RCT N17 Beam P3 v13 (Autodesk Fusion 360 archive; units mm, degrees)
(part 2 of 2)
sketch "Sketch1" plane through (0, 0, 0) normal (0, 0, 1) x axis (1, 0, 0)
  line L1 (-16, -1.6) -> (-12, -1.6)
  line L2 (-16, 1.6) -> (-16, -1.6)
  line L3 (-12, 1.6) -> (-16, 1.6)
  line L4 (-12, -1.6) -> (-12, 1.6)
  line L5 (0, 1.73) -> (0, 2.6)
  line L6 (0, -1.73) -> (0, -2.6)
  line L7 (0, 4.3) -> (0, 2.6)
  line L8 (0, -4.3) -> (0, -2.6)
  line L9 (-7, 1.6) -> (-12, 1.6)
  line L10 (-7, -1.6) -> (-12, -1.6)
  line L11 (-7, -1.6) -> (-7, 1.6)
  line L12 (-4, 1.6) -> (-7, 1.6)
  line L13 (-4, -1.6) -> (-4, 1.6)
  line L14 (-7, -1.6) -> (-4, -1.6)
  line L15 (-4, 3.3) -> (-4, 1.6)
  line L16 (-16, 3.3) -> (-4, 3.3)
  line L17 (-16, 1.6) -> (-16, 3.3)
  line L18 (-16, 0) -> (0, 0)
  line L19 (-12, 3.3) -> (-12, 1.6)
  line L20 (-7, 3.3) -> (-7, 1.6)
  line L21 (-2.7568, 3.3) -> (-4, 3.3)
  line L22 (3.43, -3.43) -> (-3.43, -3.43)
  line L23 (3.43, 3.43) -> (3.43, -3.43)
  line L24 (-3.43, 3.43) -> (3.43, 3.43)
  line L25 (-3.43, -3.43) -> (-3.43, 3.43)
  line L26 (3.43, 3.43) -> (-3.43, -3.43)
  line L27 (-3.43, 3.43) -> (3.43, -3.43)
  circle C1 centre (0, 0) radius 1.625
  circle C2 centre (0, 0) radius 3
  circle C3 centre (0, 0) radius 2.6
  circle C4 centre (0, 0) radius 1.73
  circle C5 centre (0, 0) radius 4.3
  point P1 (0, 0)
  point P2 (0, 0)
  point P5 (0, 0)
  point P10 (0, 2.6)
  point P11 (0, -2.6)
  point P12 (0, 1.73)
  point P13 (0, -1.73)
  point P14 (-12, 0)
  point P3 (0, 0)
  point P4 (0, 0)
  point P15 (0, 0)
  point P16 (0, 4.3)
  point P17 (0, -4.3)
  point P18 (-7, -1.6)
  point P21 (-7, -1.6)
  point P8 (-16, 1.6)
  point P24 (-16, 1.6)
  point P25 (0, 0)
  point P26 (-16, 0)
  point P27 (-12, 3.3)
  point P28 (-7, 3.3)
  point P30 (-2.7568, 3.3)
  point P35 (0, 0)
  point P36 (0, -3.43)
  point P37 (0, -1.73)
  point P7 (-16, -1.6)
  point P9 (-12, 1.6)
  point P20 (-4, -1.6)
  point P23 (-16, 3.3)
  coincident P1 P2
  concentric C1 C2
  concentric C2 C3
  coincident P1 P5
  horizontal L1
  vertical L2
  horizontal L3
  coincident C3 P10
  coincident C3 P11
  coincident C4 P12
  coincident C4 P13
  vertical L4
  midpoint L4 P14
  coincident P3 L5
  coincident P4 L6
  vertical L5
  vertical L6
  horizontal P1 P14
  coincident P1 P15
  coincident C5 P16
  vertical L7
  coincident C5 P17
  parallel L7 L8
  perpendicular L4 L9
  perpendicular L4 L10
  perpendicular L11 L12
  perpendicular L12 L13
  perpendicular L13 L14
  coincident P18 P21
  perpendicular L12 L15
  perpendicular L15 L16
  perpendicular L16 L17
  coincident P8 P24
  coincident P2 P25
  midpoint L2 P26
  coincident L16 P27
  perpendicular L16 L19
  coincident L16 P28
  perpendicular L16 L20
  vertical L20
  coincident C5 P30
  perpendicular L15 L21
  perpendicular L22 L23
  parallel L22 L24
  parallel L23 L25
  horizontal L22
  coincident L26 P35
  coincident L27 P35
  coincident P5 P35
  midpoint L22 P36
  coincident P13 P37
  equal L22 L25
  dimension "d1" diameter C1 = 3.25
  dimension "d2" diameter C2 = 6
  dimension "d3" diameter C3 = 5.2 (= "heatset_entry")
  dimension "d4" distance C3 C4 = 0.87 (= "print_wall * 2")
  dimension "d11" distance P7 P8 = 3.2 (= "recip_thickness")
  dimension "d29" distance P8 P9 = 4
  dimension "d69" distance P11 P17 = 1.7
  dimension "d70" distance L4 P18 = 5
  dimension "d71" distance P20 P21 = 3
  dimension "d72" distance P23 P24 = 1.7
  dimension "d95" distance P15 L13 = 4
  dimension "d99" distance P36 P37 = 1.7
  dimension "d104" distance P15 L22 = 3.43
extrude "Extrude7" new body sketch "Sketch1" profile of C3 C4 L2 L3 L4 L5 L6 C5 L7 L8 L9 L11 L12 L13 L14 L15 L16 L17 L18 L19 L20 L21 along normal blind 8 (= "heatset_depth + 4 mm")
extrude "Extrude9" cut sketch "Sketch1" profile of C3 C4 L5 L6 L18 along normal blind 4 (= "heatset_depth")
chamfer "Chamfer8" distance 0.2 (= "heatset_taperby") distance 4 (= "heatset_depth")
chamfer "Chamfer9" distance 0.4
extrude "Extrude8" sketch "Sketch1" profile of L4 C5 L9 L11 L16 L18 L19 L20 blind -4
extrude "Extrude10" sketch "Sketch1" profile of L9 L16 L19 L20 blind 1
extrude "Extrude11" sketch "Sketch1" profile of L3 L16 L17 L19 blind 1
fillet "Fillet12" radius 2
fillet "Fillet13" radius 2
fillet "Fillet14" radius 10
mirror "Mirror2"
combine "Combine2"
chamfer "Chamfer10" distance 0.87
copy_paste_bodies "CopyPasteBodies2"
move "Move2"
mirror "Mirror4"
combine "Combine5"
extrude "Extrude12" sketch "Sketch1" profile of C3 C4 L5 L6 C5 L7 L8 L18 L21 L22 L23 L24 L25 blind 6.25
fillet "Fillet17" radius 2
fillet "Fillet18" radius 4
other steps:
base_feature "Base Feature"

design "Beam Lock P2 Singlet"
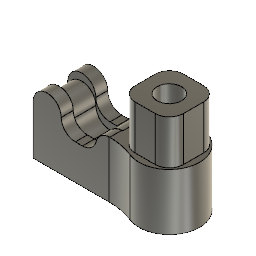
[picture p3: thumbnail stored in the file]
parameter "heatset_entry" = 5.2
parameter "heatset_depth" = 4
parameter "heatset_taperby" = 0.2
parameter "recip_thickness" = 3.2
parameter "recip_slotwidth" = 7
parameter "print_wall" = 0.435 (= "( 0.87 / 2 ) * 1 mm")
parameter "recip_distfrom" = 4.5
parameter "recip_tooth" = 1 comment "extra length to lock-in"
parameter "recip_slotdepth" = 10
sketch "Sketch1" plane through (0, 0, 0) normal (0, 0, 1) x axis (1, 0, 0)
  line L1 (-16, -1.6) -> (-12, -1.6)
  line L2 (-16, 1.6) -> (-16, -1.6)
  line L3 (-12, 1.6) -> (-16, 1.6)
  line L4 (-12, -1.6) -> (-12, 1.6)
  line L5 (0, 1.73) -> (0, 2.6)
  line L6 (0, -1.73) -> (0, -2.6)
  line L7 (0, 4.3) -> (0, 2.6)
  line L8 (0, -4.3) -> (0, -2.6)
  line L9 (-7, 1.6) -> (-12, 1.6)
  line L10 (-7, -1.6) -> (-12, -1.6)
  line L11 (-7, -1.6) -> (-7, 1.6)
  line L12 (-4, 1.6) -> (-7, 1.6)
  line L13 (-4, -1.6) -> (-4, 1.6)
  line L14 (-7, -1.6) -> (-4, -1.6)
  line L15 (-4, 3.3) -> (-4, 1.6)
  line L16 (-16, 3.3) -> (-4, 3.3)
  line L17 (-16, 1.6) -> (-16, 3.3)
  line L18 (-16, 0) -> (0, 0)
  line L19 (-12, 3.3) -> (-12, 1.6)
  line L20 (-7, 3.3) -> (-7, 1.6)
  line L21 (-2.7568, 3.3) -> (-4, 3.3)
  line L22 (3.43, -3.43) -> (-3.43, -3.43)
  line L23 (3.43, 3.43) -> (3.43, -3.43)
  line L24 (-3.43, 3.43) -> (3.43, 3.43)
  line L25 (-3.43, -3.43) -> (-3.43, 3.43)
  line L26 (3.43, 3.43) -> (-3.43, -3.43)
  line L27 (-3.43, 3.43) -> (3.43, -3.43)
  circle C1 centre (0, 0) radius 1.625
  circle C2 centre (0, 0) radius 3
  circle C3 centre (0, 0) radius 2.6
  circle C4 centre (0, 0) radius 1.73
  circle C5 centre (0, 0) radius 4.3
  point P1 (0, 0)
  point P2 (0, 0)
  point P5 (0, 0)
  point P10 (0, 2.6)
  point P11 (0, -2.6)
  point P12 (0, 1.73)
  point P13 (0, -1.73)
  point P14 (-12, 0)
  point P3 (0, 0)
  point P4 (0, 0)
  point P15 (0, 0)
  point P16 (0, 4.3)
  point P17 (0, -4.3)
  point P18 (-7, -1.6)
  point P21 (-7, -1.6)
  point P8 (-16, 1.6)
  point P24 (-16, 1.6)
  point P25 (0, 0)
  point P26 (-16, 0)
  point P27 (-12, 3.3)
  point P28 (-7, 3.3)
  point P30 (-2.7568, 3.3)
  point P35 (0, 0)
  point P36 (0, -3.43)
  point P37 (0, -1.73)
  point P7 (-16, -1.6)
  point P9 (-12, 1.6)
  point P20 (-4, -1.6)
  point P23 (-16, 3.3)
  coincident P1 P2
  concentric C1 C2
  concentric C2 C3
  coincident P1 P5
  horizontal L1
  vertical L2
  horizontal L3
  coincident C3 P10
  coincident C3 P11
  coincident C4 P12
  coincident C4 P13
  vertical L4
  midpoint L4 P14
  coincident P3 L5
  coincident P4 L6
  vertical L5
  vertical L6
  horizontal P1 P14
  coincident P1 P15
  coincident C5 P16
  vertical L7
  coincident C5 P17
  parallel L7 L8
  perpendicular L4 L9
  perpendicular L4 L10
  perpendicular L11 L12
  perpendicular L12 L13
  perpendicular L13 L14
  coincident P18 P21
  perpendicular L12 L15
  perpendicular L15 L16
  perpendicular L16 L17
  coincident P8 P24
  coincident P2 P25
  midpoint L2 P26
  coincident L16 P27
  perpendicular L16 L19
  coincident L16 P28
  perpendicular L16 L20
  vertical L20
  coincident C5 P30
  perpendicular L15 L21
  perpendicular L22 L23
  parallel L22 L24
  parallel L23 L25
  horizontal L22
  coincident L26 P35
  coincident L27 P35
  coincident P5 P35
  midpoint L22 P36
  coincident P13 P37
  equal L22 L25
  dimension "d1" diameter C1 = 3.25
  dimension "d2" diameter C2 = 6
  dimension "d3" diameter C3 = 5.2 (= "heatset_entry")
  dimension "d4" distance C3 C4 = 0.87 (= "print_wall * 2")
  dimension "d11" distance P7 P8 = 3.2 (= "recip_thickness")
  dimension "d29" distance P8 P9 = 4
  dimension "d69" distance P11 P17 = 1.7
  dimension "d70" distance L4 P18 = 5
  dimension "d71" distance P20 P21 = 3
  dimension "d72" distance P23 P24 = 1.7
  dimension "d95" distance P15 L13 = 4
  dimension "d99" distance P36 P37 = 1.7
  dimension "d104" distance P15 L22 = 3.43
extrude "Extrude7" new body sketch "Sketch1" profile of C3 C4 L2 L3 L4 L5 L6 C5 L7 L8 L9 L11 L12 L13 L14 L15 L16 L17 L18 L19 L20 L21 along normal blind 8 (= "heatset_depth + 4 mm")
extrude "Extrude9" cut sketch "Sketch1" profile of C3 C4 L5 L6 L18 along normal blind 4 (= "heatset_depth")
chamfer "Chamfer8" distance 0.2 (= "heatset_taperby") distance 4 (= "heatset_depth")
chamfer "Chamfer9" distance 0.4
extrude "Extrude8" sketch "Sketch1" profile of L4 C5 L9 L11 L16 L18 L19 L20 blind -4
extrude "Extrude10" sketch "Sketch1" profile of L9 L16 L19 L20 blind 1
extrude "Extrude11" sketch "Sketch1" profile of L3 L16 L17 L19 blind 1
fillet "Fillet12" radius 2
fillet "Fillet13" radius 2
fillet "Fillet14" radius 10
mirror "Mirror2"
combine "Combine2"
chamfer "Chamfer10" distance 0.87
extrude "Extrude12" sketch "Sketch1" profile of C3 C4 L5 L6 C5 L7 L8 L18 L21 L22 L23 L24 L25 blind 6.25
fillet "Fillet17" radius 2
